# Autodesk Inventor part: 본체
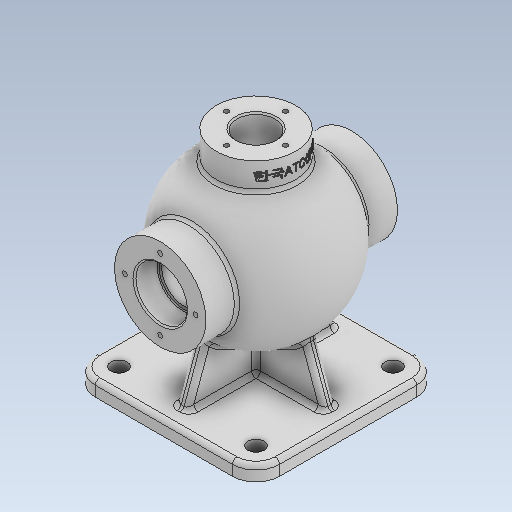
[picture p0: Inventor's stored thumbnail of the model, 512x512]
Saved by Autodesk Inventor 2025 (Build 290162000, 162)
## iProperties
Created: 2024-07
Part Number: 본체
Material: 일반
Document SubType Name: Modeling
Designer: 미서니
Density: 1 g/cm^3
Appearance: 기본값
Author: 미서니
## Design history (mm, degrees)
sketch "스케치1"
  geometry: L1 (0, -75.794)-(0, 75.794); A1 r 54 centre (0, 0) between (0, 54) and (0, -54); 4 further points
  constraints: 2 coincident, 2 end point, 2 point on circle, 2 point on line, 1 centre point, 1 midpoint, 1 vertical
  dimensions: "d3" = 54 radius of A1
revolve "회전1" sketch "스케치1" stored, may be unused: angle "d1" = 90 deg
sketch "스케치2"
  geometry: C1 r 31 at (0, 0); 1 further point
  constraints: 1 centre point, 1 coincident
  dimensions: "d2" = 62 diameter of C1
extrude "돌출1" join sketch "스케치2" stored distance "d4" = 130; taper "d5" = 0 deg
sketch "스케치3"
  geometry: C1 r 27 at (0, 0); 1 further point
  constraints: 1 centre point, 1 coincident
  dimensions: "d6" = 54 diameter of C1
extrude "돌출2" join sketch "스케치3" distance "d7" = 65; taper "d8" = 0 deg
node "작업 평면1"
sketch "스케치4"
  geometry: L1 (62.5, -62.5)-(-62.5, -62.5); L2 (-62.5, -62.5)-(-62.5, 62.5); L3 (-62.5, 62.5)-(62.5, 62.5); L4 (62.5, 62.5)-(62.5, -62.5); L5 (62.5, -62.5)-(-62.5, 62.5); L6 (-62.5, -62.5)-(62.5, 62.5); 1 further point
  constraints: 12 end point, 2 midpoint, 2 parallel, 1 horizontal, 1 perpendicular
  dimensions: "d10" = 125 distance of L2.end L3.end; "d11" = 125 distance of L1.end L2.end
extrude "돌출3" join sketch "스케치4" distance "d12" = 10; taper "d13" = 0 deg
fillet "모깎기1" dims "d14" = 16
node "작업 평면2"
sketch "스케치5"
  geometry: L1 (50.5, 4)-(-50.5, 4); L2 (-50.5, 4)-(-50.5, -4); L3 (-50.5, -4)-(50.5, -4); L4 (50.5, -4)-(50.5, 4); L5 (50.5, 4)-(-50.5, -4); L6 (-50.5, 4)-(50.5, -4); L7 (4, 50.5)-(-4, 50.5); L8 (-4, 50.5)-(-4, -50.5); L9 (-4, -50.5)-(4, -50.5); L10 (4, -50.5)-(4, 50.5); L11 (4, 50.5)-(-4, -50.5); L12 (-4, 50.5)-(4, -50.5); L13 (-62.5, 46.5)-(-62.5, -46.5) reference; L14 (-46.5, -62.5)-(46.5, -62.5) reference; L15 (46.5, 62.5)-(-46.5, 62.5) reference; 5 further points
  constraints: 24 end point, 4 midpoint, 4 parallel, 2 horizontal, 2 perpendicular
  dimensions: "d16" = 8 distance of L1.end L2.end; "d17" = 8 distance of L7.start L7.end; "d18" = 12 distance between parallel lines of L13 L2; "d19" = 12 distance between parallel lines of L14 L9; "d115" = 12 distance between parallel lines of L7 L15 (derived)
extrude "돌출4" join sketch "스케치5" stored distance "d20" = 10; taper "d21" = 0 deg
feature "면 기울기1" dims angle "d22" = 20 deg
fillet "모깎기2" dims "d23" = 3
fillet "모깎기3" dims "d24" = 3
sketch "스케치6"
  geometry: L1 (0, 159.291)-(0, -194.33); A1 r 44 centre (0, 0) between (0, 44) and (0, -44); 1 further point
  constraints: 3 point on line, 2 end point, 2 point on circle, 1 centre point, 1 coincident, 1 vertical
  dimensions: "d25" = 44 radius of A1
revolve "회전2" sketch "스케치6" stored, may be unused: angle "d26" = 90 deg
sketch "스케치7"
  geometry: C1 r 31 at (0, 0) reference; 2 further points
  constraints: 1 coincident
hole "구멍1" sketch "스케치7" at (0, 0) diameter "d27" = 30; stored, may be unused: countersink angle "d31" = 90 deg, drill point angle "d33" = 0 deg; dims "d28" = 6, "d29" = 4, "d30" = 2, "d32" = 8
sketch "스케치9"
  geometry: C1 r 31 at (0, 0) reference; 2 further points
  constraints: 1 coincident
hole "구멍3" sketch "스케치9" at (0, 0) diameter "d41" = 35; stored, may be unused: countersink angle "d45" = 90 deg, drill point angle "d47" = 0 deg; dims "d42" = 6, "d43" = 4, "d44" = 2, "d46" = 16
sketch "스케치10"
  geometry: C1 r 31 at (0, 0) reference; 2 further points
  constraints: 1 coincident
hole "구멍4" sketch "스케치10" at (0, 0) diameter "d48" = 35; stored, may be unused: countersink angle "d52" = 90 deg, drill point angle "d54" = 0 deg; dims "d49" = 6, "d50" = 4, "d51" = 2, "d53" = 16
sketch "스케치11"
  geometry: C1 r 27 at (0, 0) reference; 2 further points
  constraints: 1 coincident
hole "구멍5" sketch "스케치11" at (0, 0) diameter "d63" = 26; stored, may be unused: countersink angle "d67" = 90 deg, drill point angle "d69" = 0 deg; dims "d64" = 6, "d65" = 4, "d66" = 2, "d68" = 16
chamfer "모따기1" distance "d70" = 1; stored, may be unused: second distance "d71" = 2, angle "d72" = 45 deg
fillet "모깎기4" dims "d73" = 0.6
sketch "스케치12" dims "d74" = 48
  geometry: L1 (0, 0)-(0, 24); 1 further point
  constraints: 2 end point, 1 coincident, 1 vertical, 1 vertical alignment, 2 other
sketch "스케치13" dims "d75" = 48
  geometry: L1 (0, 0)-(0, 24); 1 further point
  constraints: 2 end point, 1 coincident, 1 vertical, 1 vertical alignment, 2 other
hole "구멍6" sketch "스케치12" diameter "d76" = 3.242; stored, may be unused: countersink angle "d80" = 90 deg, drill point angle "d82" = 120 deg; dims "d77" = 12, "d78" = 4, "d79" = 2, "d81" = 15
hole "구멍7" sketch "스케치13" diameter "d83" = 3.242; stored, may be unused: countersink angle "d87" = 90 deg, drill point angle "d89" = 120 deg; dims "d84" = 12, "d85" = 4, "d86" = 2, "d88" = 15
sketch "스케치14" dims "d93" = 40
  geometry: L1 (0, 0)-(0, -20); 1 further point
  constraints: 2 end point, 1 coincident, 1 vertical, 1 vertical alignment, 2 other
hole "구멍8" sketch "스케치14" at (0, -20) diameter "d94" = 3.242; stored, may be unused: countersink angle "d98" = 90 deg, drill point angle "d100" = 120 deg; dims "d95" = 9, "d96" = 4, "d97" = 2, "d99" = 11
sketch "스케치16"
  geometry: A1 r 13 centre (46.5, -46.5) between (46.5, -59.5) and (59.5, -46.5) reference; A2 r 13 centre (46.5, 46.5) between (59.5, 46.5) and (46.5, 59.5) reference; A3 r 13 centre (-46.5, -46.5) between (-59.5, -46.5) and (-46.5, -59.5) reference; A4 r 13 centre (-46.5, 46.5) between (-46.5, 59.5) and (-59.5, 46.5) reference; 5 further points
  constraints: 4 coincident
hole "구멍9" sketch "스케치16" at (46.5, -46.5), (46.5, 46.5), (-46.5, -46.5), (-46.5, 46.5) diameter "d104" = 11; stored, may be unused: countersink angle "d108" = 90 deg, drill point angle "d110" = 0 deg; dims "d105" = 9, "d106" = 4, "d107" = 2, "d109" = 11
node "작업 평면3"
sketch "스케치17"
  geometry: L1 (65, -27)-(65, 27) reference; 2 further points
  constraints: 1 horizontal alignment, 1 other
  dimensions: "d112" = 9 distance from line of point (56, 0) L1
feature "엠보싱1" sketch "스케치17" dims "d3" = 54, "d10" = 125, "d11" = 125, "d113" = 0.5, "d114" = 0
node "솔리드1"
pattern_circular "원형 패턴1" dims "d91" = 360 deg
pattern_circular "원형 패턴2" dims angle "d102" = 360 deg
feature "A9D066F2-1C7D-4E18-AEED-F7BC21143FA4" dims "d27" = 30, "d28" = 6, "d29" = 4, "d30" = 2, "d31" = 90 deg, "d32" = 8, "d33" = 0
other parameters: "d9" = -85, "d55" = 0.5, "d56" = 2, "d57" = 0, "d59" = 0.5, "d60" = 2, "d61" = 0
